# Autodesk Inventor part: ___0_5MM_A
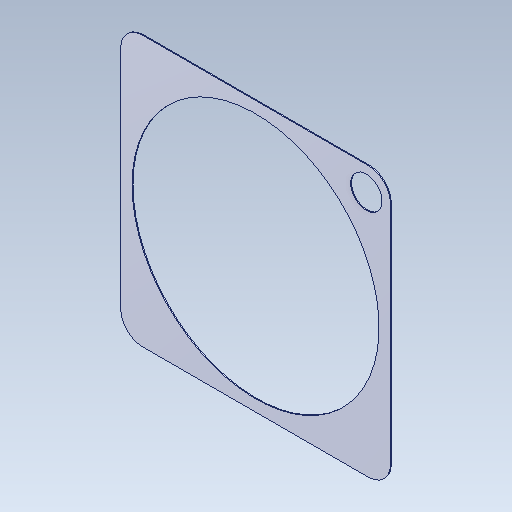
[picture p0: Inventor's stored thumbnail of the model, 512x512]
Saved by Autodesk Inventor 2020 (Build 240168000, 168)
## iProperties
Created: 2017-09
Part Number: ___0_5MM_A
Material: Générique
Document SubType Name: Modeling
Designer: bruno
Density: 1 g/cm^3
Appearance: Par défaut
Author: bruno
Sending System: SolidWorks 2016
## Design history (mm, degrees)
feature "Importée1"
node "Solide1"
